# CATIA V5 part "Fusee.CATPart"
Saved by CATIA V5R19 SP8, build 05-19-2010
Part number: Fusee
Bounding box of the stored display mesh (mm): x 370.039 to 540, y -40 to 160, z -340 to 20
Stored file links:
  C:\Users\ThinkMotion\Desktop\EU_thinkMotion\iao\IAO_MMS_Groupe3\rdalborgo\rdalborgo\Fusee.CATPart
  C:\Users\ThinkMotion\Desktop\EU_thinkMotion\iao\IAO_MMS_Groupe3\rdalborgo\rdalborgo\rdalborgo.CATProduct
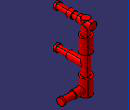
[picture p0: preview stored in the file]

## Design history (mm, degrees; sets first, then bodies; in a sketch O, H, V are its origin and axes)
External parameters (linked from other documents)
  `External.Axe inter diam` = 30 mm
  `External.Deport bielle bati` = 165 mm
  `External.Deport bielle verin` = 70 mm
  `External.Deport bielle fusee` = 120 mm
  `External.Demi epaisseur tete bielle` = 30 mm
  `External.Demi epaisseur bielle` = 20 mm
  `External.Demi epaisseur tete verin` = 15 mm
  `External.Deport de roue` = 100 mm
Set1
  Plane1: linked copy from another document
  Line1: linked copy from another document
  Point1 "B fusee": linked copy from another document
  Point2 "Inf fusee": linked copy from another document
  Line2: linked copy from another document
  Point3 "Origine": linked copy from another document
  Point4 "B verin": linked copy from another document
  Plane2: linked copy from another document
  Line3: linked copy from another document
  Plane3: linked copy from another document
  Line4: linked copy from another document
  Line5: linked copy from another document
Body1 (main body)
  Sketch1 on Plane1, origin (400, 0, 0), H (0, 1, 0), V (0, 0, 1)
    line L1 (120, 20) -> (140, 20)
    line L2 (140, 20) -> (140, -60)
    line L3 (140, -60) -> (150, -60)
    line L4 (150, -60) -> (150, -140)
    line L5 (150, -140) -> (140, -140)
    point P6 (140, -140)
    line L6 (140, -140) -> (140, -250)
    line L7 (140, -250) -> (150, -250)
    point P8 (150, -250)
    line L8 (150, -250) -> (150, -340)
    line L9 (150, -340) -> (120, -340)
    line L10 (120, -340) -> (120, 20)
    reference projected line E1 (120, 0) -> (120, -310) from Line1
    reference projected point E2 (120, 0) from Point1
    reference projected point E3 (120, -310) from Point2
    distance L10 L4 = 30
    distance L10 L6 = 20
    distance L1 E2 = 20
    distance L9 E3 = 30
    distance L1 L3 = 80
    distance L3 L5 = 80
    distance L7 L9 = 90
    horizontal: L1 H, L3 H, L5 H, L7 H, L9 H
    vertical: L2 V, L4 V, L6 V, L8 V, L10 V
    coincidence: P6 L2, P8 L4, L4 L8, L2 L6, L10 E1
  Shaft1: profile Sketch1, axis Line1, angle 360
  Sketch2 on Plane1, origin (400, 0, 0), H (0, 1, 0), V (0, 0, 1)
    line L1 (160, 20) -> (85, 20)
    line L2 (85, 20) -> (85, 15)
    line L3 (85, 15) -> (55, 15)
    line L4 (55, 15) -> (55, 20)
    line L5 (55, 20) -> (30, 20)
    line L6 (30, 20) -> (30, 15)
    point P7 (30, 15)
    line L7 (30, 15) -> (-30, 15)
    line L8 (-30, 15) -> (-30, 20)
    line L9 (-30, 20) -> (-40, 20)
    line L10 (-40, 20) -> (-40, 0)
    line L11 (-40, 0) -> (160, 0)
    line L12 (160, 0) -> (160, 20)
    reference projected line E1 (100, 0) -> (140, 0) from Line2
    reference projected line E2 (100, 0) -> (140, 0) from Line2
    reference projected point E3 (0, 0) from Point3
    reference projected point E4 (70, 0) from Point4
    distance L7 L11 = 15 {= `External.Axe inter diam` /2}
    distance L1 E2 = 20 {= (`External.Axe inter diam` +10mm)/2}
    distance L6 L8 = 60 {= `External.Demi epaisseur tete bielle` *2}
    distance L8 E3 = 30 {= `External.Demi epaisseur tete bielle`}
    distance L4 L2 = 30 {= `External.Demi epaisseur tete verin` *2}
    distance L4 E4 = 15 {= `External.Demi epaisseur tete verin`}
    distance L10 L8 = 10
    distance L12 L10 = 200 {= `External.Deport bielle bati` +35mm}
    horizontal: L1 H, L3 H, L5 H, L7 H, L9 H, L11 H
    vertical: L2 V, L4 V, L6 V, L8 V, L10 V, L12 V
    coincidence: P7 L3, L11 E1, L1 L5, L9 L5, L7 L3
  Shaft2: profile Sketch2, axis Line2, angle 360
  Sketch3 on Plane2, origin (400, 0, 0), H (0, 1, 0), V (0, 0, 1)
    line L1 (120, -200) -> (-40, -200)
    line L2 (-40, -200) -> (-40, -180)
    line L3 (-40, -180) -> (-30, -180)
    line L4 (-30, -180) -> (-30, -185)
    line L5 (-30, -185) -> (30, -185)
    line L6 (30, -185) -> (30, -180)
    line L7 (30, -180) -> (120, -180)
    line L8 (120, -180) -> (120, -200)
    reference projected line E1 (100, -200) -> (140, -200) from Line3
    reference projected line E2 (120, 0) -> (120, -310) from Line1
    reference projected point E3 (0, 0) from Point3
    distance L8 L2 = 160 {= `External.Deport bielle fusee` +40mm}
    distance L7 L1 = 20 {= (`External.Axe inter diam` +10mm)/2}
    distance L4 L6 = 60 {= `External.Demi epaisseur tete bielle` *2}
    distance L4 E3 = 30 {= `External.Demi epaisseur tete bielle`}
    distance L5 L1 = 15 {= `External.Axe inter diam` /2}
    horizontal: L1 H, L3 H, L5 H, L7 H
    vertical: L2 V, L4 V, L6 V, L8 V
    coincidence: L1 E1, L8 E2, L3 L7
  Shaft3: profile Sketch3, axis Line3, angle 360
  Sketch4 on Plane3, origin (0, 120, 0), H (-1, 0, 0), V (0, 0, 1)
    line L1 (-400, -310) -> (-540, -310)
    line L2 (-540, -310) -> (-540, -290)
    line L3 (-540, -290) -> (-530, -290)
    line L4 (-530, -290) -> (-530, -295)
    line L5 (-530, -295) -> (-470, -295)
    line L6 (-470, -295) -> (-470, -290)
    point P7 (-470, -290)
    line L7 (-470, -290) -> (-400, -290)
    line L8 (-400, -290) -> (-400, -310)
    reference projected line E1 (-400, 0) -> (-400, -310) from Line1
    reference projected line E2 (-400, -310) -> (-500, -310) from Line4
    reference projected line E3 (-500, -310) -> (-500, -110) from Line5
    distance L2 L8 = 140 {= `External.Deport de roue` +40mm}
    distance L7 L1 = 20 {= (`External.Axe inter diam` +10mm)/2}
    distance L5 L1 = 15 {= `External.Axe inter diam` /2}
    distance L4 L6 = 60
    distance E3 L6 = 30
    horizontal: L1 H, L3 H, L5 H, L7 H
    vertical: L2 V, L4 V, L6 V, L8 V
    coincidence: P7 L3, E1 L8, L1 E2
  Shaft4: profile Sketch4, axis Line4, angle 360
